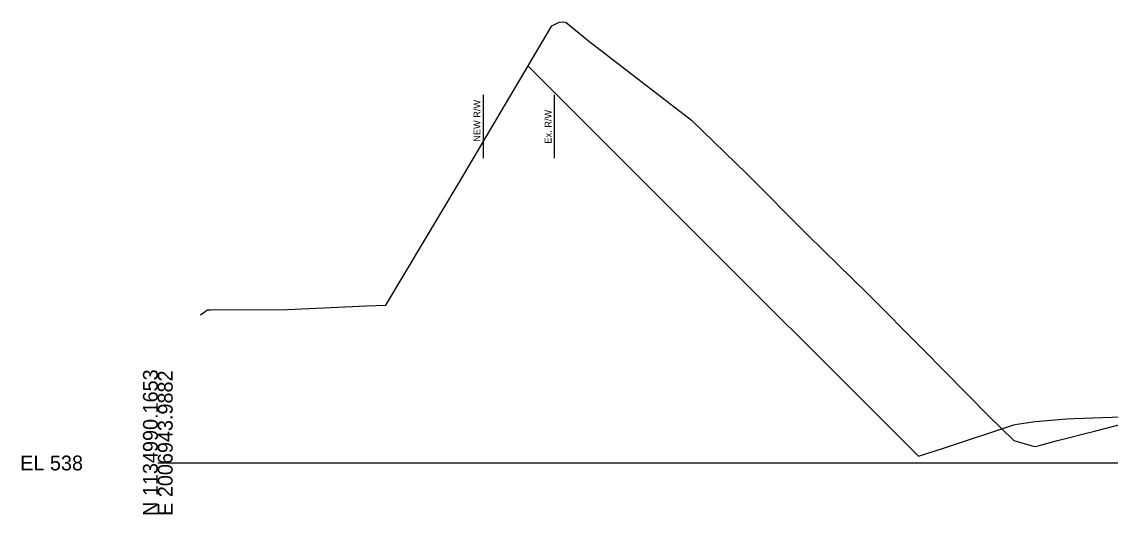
# Model space of a CAD drawing. Extents: x -201 to 2007062, y -213 to 1139737.
# Drawn here: x 974.3 to 1179.9, y 990.3 to 1083.4 of the extents above; entities that cross this region are included whole.
import ezdxf

# ---------------------------------------------------------------- set-up
doc = ezdxf.new("R2010")
doc.units = 0
for name, color, linetype in [('Default', 7, 'Continuous'), ('RD_DTM_Design_FG', 7, 'Continuous'), ('RD_GPK_XS_Cell', 7, 'Continuous'), ('RD_XS_ExGround', 7, 'Continuous'), ('RD_XS_ExRW', 7, 'Continuous'), ('RD_XS_NewRW', 7, 'Continuous')]:
    doc.layers.add(name, color=color, linetype=linetype)

msp = doc.modelspace()

# ---------------------------------------------------------------- linework, layer by layer
at = {"layer": 'RD_DTM_Design_FG'}
msp.add_lwpolyline([(1069.88, 1075.08), (1095.05, 1049.89), (1143.64, 1001.26), (1148.38, 1002.83), (1161.65, 1007.23), (1162.29, 1007.33), (1165.65, 1007.87), (1166.43, 1007.93), (1171.66, 1008.34), (1172.95, 1008.39), (1183.82, 1008.8), (1187.67, 1008.95), (1189.12, 1008.83), (1196, 1009.37)], dxfattribs=at)
at = {"layer": 'RD_GPK_XS_Cell'}
msp.add_line((1000, 1000), (1250, 1000), dxfattribs=at)
at = {"layer": 'RD_XS_ExGround'}
msp.add_lwpolyline([(1008.06, 1028), (1009.36, 1028.93), (1010.01, 1028.94), (1024.49, 1029), (1039.38, 1029.71), (1043.03, 1029.83), (1056.88, 1053.01), (1074.39, 1082.61), (1075.79, 1083.32), (1076.61, 1083.4), (1077.12, 1083.25), (1081.36, 1079.8), (1100.76, 1064.8), (1111.29, 1054.59), (1122.82, 1043.01), (1134.04, 1032.04), (1144.46, 1021.52), (1156.92, 1008.83), (1161.63, 1004.25), (1165.09, 1003.26), (1165.7, 1003.09), (1166.27, 1003.25), (1169.64, 1004.19), (1177.12, 1006.09), (1185.14, 1008.13)], dxfattribs=at)
at = {"layer": 'RD_XS_ExRW'}
msp.add_line((1074.85, 1069.61), (1074.85, 1057.61), dxfattribs=at)
at = {"layer": 'RD_XS_NewRW'}
msp.add_line((1061.45, 1069.61), (1061.45, 1057.61), dxfattribs=at)

# ---------------------------------------------------------------- texts
at = {"layer": 'Default'}
msp.add_text('-', height=0.0001, dxfattribs=at).set_placement((1000, 1000))
at = {"layer": 'RD_GPK_XS_Cell'}
for s, p in [('N 1134990.1653', (1000, 990)), ('E 2006943.9882', (1002.8, 990))]:
    msp.add_text(s, height=2.8, rotation=90, dxfattribs=at).set_placement(p)
msp.add_text('EL 538', height=2.8, dxfattribs=at).set_placement((974, 998.6))
at = {"layer": 'RD_XS_ExRW'}
msp.add_text('Ex. R/W ', height=1.3, rotation=90, dxfattribs=at).set_placement((1074.35, 1060.37))
at = {"layer": 'RD_XS_NewRW'}
msp.add_text('NEW R/W ', height=1.3, rotation=90, dxfattribs=at).set_placement((1060.92, 1060.72))

doc.saveas('drawing.dxf')
